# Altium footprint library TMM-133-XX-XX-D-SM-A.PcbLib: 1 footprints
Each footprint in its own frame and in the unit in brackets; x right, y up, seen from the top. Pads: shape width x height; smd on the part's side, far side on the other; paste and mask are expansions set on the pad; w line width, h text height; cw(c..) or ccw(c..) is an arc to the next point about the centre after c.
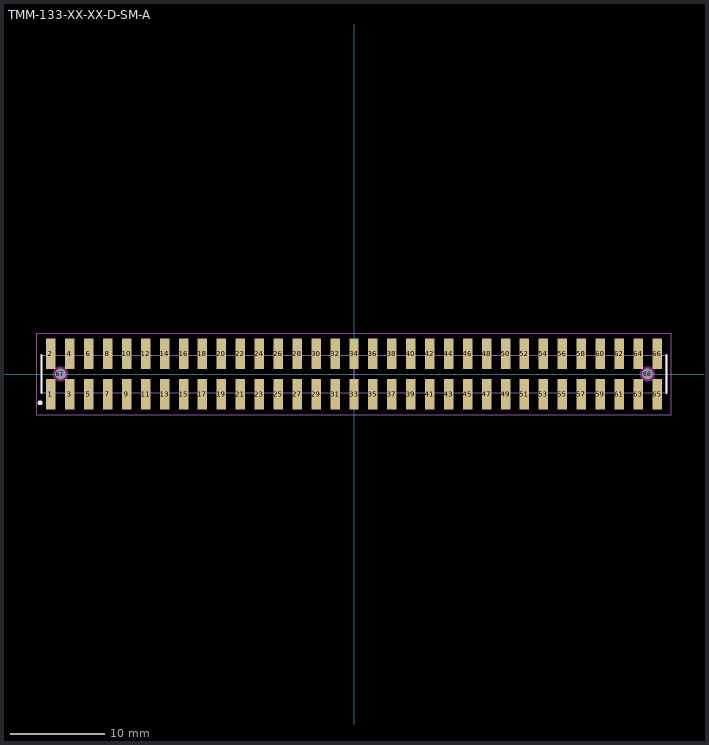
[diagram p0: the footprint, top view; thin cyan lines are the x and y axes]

## TMM-133-XX-XX-D-SM-A [mm] "2.00mm pitch, 66 pin, terminal strip; double row, w/alignment pins, SMT"
height 2.77
pads (68):
  rect 1x3.2 smd mask+0: 1(-32,-2.15) 2(-32,2.15) 3(-30,-2.15) 4(-30,2.15) 5(-28,-2.15) 6(-28,2.15) 7(-26,-2.15) 8(-26,2.15) 9(-24,-2.15) 10(-24,2.15) 11(-22,-2.15) 12(-22,2.15) 13(-20,-2.15) 14(-20,2.15) 15(-18,-2.15) 16(-18,2.15) 17(-16,-2.15) 18(-16,2.15) 19(-14,-2.15) 20(-14,2.15) 21(-12,-2.15) 22(-12,2.15) 23(-10,-2.15) 24(-10,2.15) 25(-8,-2.15) 26(-8,2.15) 27(-6,-2.15) 28(-6,2.15) 29(-4,-2.15) 30(-4,2.15) 31(-2,-2.15) 32(-2,2.15) 33(0,-2.15) 34(0,2.15) 35(2,-2.15) 36(2,2.15) 37(4,-2.15) 38(4,2.15) 39(6,-2.15) 40(6,2.15) 41(8,-2.15) 42(8,2.15) 43(10,-2.15) 44(10,2.15) 45(12,-2.15) 46(12,2.15) 47(14,-2.15) 48(14,2.15) 49(16,-2.15) 50(16,2.15) 51(18,-2.15) 52(18,2.15) 53(20,-2.15) 54(20,2.15) 55(22,-2.15) 56(22,2.15) 57(24,-2.15) 58(24,2.15) 59(26,-2.15) 60(26,2.15) 61(28,-2.15) 62(28,2.15) 63(30,-2.15) 64(30,2.15) 65(32,-2.15) 66(32,2.15)
  round 1 hole 1.2 unplated mask+0: 67(-31,0) 68(31,0)
Top Overlay:
  circle w0.25: c-33.15,-3.05 r0.125
  lines w0.2: -33,-2 -33,2 ; 33,-2 33,2
Keep-Out Layer:
  pour cut-out: 31.807,0 31.779,0.209 31.699,0.403 31.57,0.571 31.403,0.699 31.209,0.779 31,0.807 30.791,0.779 30.596,0.699 30.429,0.571 30.301,0.403 30.22,0.209 30.193,0 30.22,-0.209 30.301,-0.403 30.429,-0.571 30.596,-0.699 30.791,-0.779 31,-0.807 31.209,-0.779 31.403,-0.699 31.57,-0.571 31.699,-0.403 31.779,-0.209
  pour cut-out: -30.193,0 -30.22,0.209 -30.301,0.403 -30.429,0.571 -30.596,0.699 -30.791,0.779 -31,0.807 -31.209,0.779 -31.403,0.699 -31.57,0.571 -31.699,0.403 -31.779,0.209 -31.807,0 -31.779,-0.209 -31.699,-0.403 -31.57,-0.571 -31.403,-0.699 -31.209,-0.779 -31,-0.807 -30.791,-0.779 -30.596,-0.699 -30.429,-0.571 -30.301,-0.403 -30.22,-0.209
Mechanical 12:
  lines w0.001: -33,-2 -33,2 33,2 33,-2 -33,-2
Mechanical 13:
  lines w0.1: -33,-2 -33,2 33,2 33,-2 -33,-2
  text ".Designator" at 0.127,-0.127 h1.52
Mechanical 15:
  lines w0.05: -0.5,0 0.5,0 ; 0,-0.5 0,0.5 ; -33.5,-4.3 -33.5,4.3 33.5,4.3 33.5,-4.3 -33.5,-4.3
